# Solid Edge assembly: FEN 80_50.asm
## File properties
Title: Zylinder
Author: bmolnar
Template: iso assembly.asm
Last saved by: bmolnar
Revision: 12
Application: Solid Edge
Username: bmolnar
Dokumentum tartalom típus: 1
Document Number: FEN 80/50
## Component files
Kolbenstange.par
Profilrohr.par
Kit_1.par
Kit_2.par
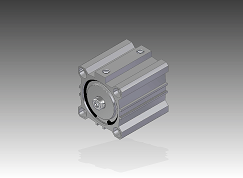
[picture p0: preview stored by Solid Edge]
